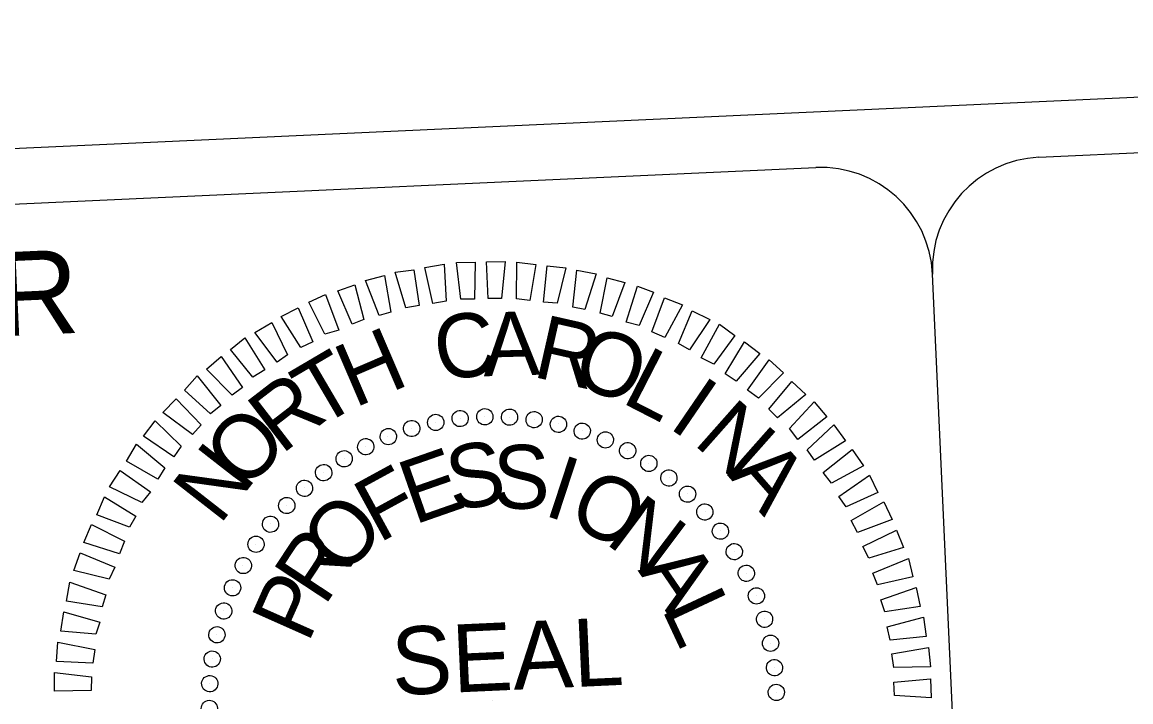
# Model space of a CAD drawing. Extents: x 1190067 to 1192950, y 891516 to 893460.
# Drawn here: x 1191805.2 to 1191884.6, y 892702.5 to 892751.2 of the extents above; entities that cross this region are included whole.
import ezdxf

# ---------------------------------------------------------------- set-up
doc = ezdxf.new("R2010")
doc.units = 0
doc.layers.add('Sheet PE Seal Cell', color=7, linetype='Continuous')
doc.layers.add('Sheet Title CELL', color=7, linetype='Continuous')

msp = doc.modelspace()

# ---------------------------------------------------------------- linework, layer by layer
at = {"layer": 'Sheet PE Seal Cell'}
for p, q in [((1191836.559, 892722.832), (1191836.559, 892722.832)), ((1191838.338, 892722.954), (1191838.338, 892722.954)), ((1191840.123, 892722.914), (1191840.123, 892722.914)), ((1191841.876, 892722.711), (1191841.876, 892722.711)), ((1191833.065, 892722.105), (1191833.065, 892722.105)), ((1191834.831, 892722.51), (1191834.831, 892722.51)), ((1191843.592, 892722.424), (1191843.592, 892722.424)), ((1191845.317, 892721.935), (1191845.317, 892721.935)), ((1191831.388, 892721.542), (1191831.388, 892721.542)), ((1191846.969, 892721.281), (1191846.969, 892721.281)), ((1191829.8, 892720.82), (1191829.8, 892720.82)), ((1191848.583, 892720.544), (1191848.583, 892720.544)), ((1191828.259, 892719.939), (1191828.259, 892719.939)), ((1191850.086, 892719.6), (1191850.086, 892719.6)), ((1191826.764, 892718.938), (1191826.764, 892718.938)), ((1191825.394, 892717.862), (1191825.394, 892717.862)), ((1191851.552, 892718.572), (1191851.552, 892718.572)), ((1191852.862, 892717.416), (1191852.862, 892717.416)), ((1191824.115, 892716.587), (1191824.115, 892716.587)), ((1191854.137, 892716.136), (1191854.137, 892716.136)), ((1191822.958, 892715.277), (1191822.958, 892715.277)), ((1191855.213, 892714.766), (1191855.213, 892714.766)), ((1191821.931, 892713.811), (1191821.931, 892713.811)), ((1191856.214, 892713.271), (1191856.214, 892713.271)), ((1191820.986, 892712.308), (1191820.986, 892712.308)), ((1191857.095, 892711.731), (1191857.095, 892711.731)), ((1191820.249, 892710.694), (1191820.249, 892710.694)), ((1191857.817, 892710.142), (1191857.817, 892710.142)), ((1191819.595, 892709.042), (1191819.595, 892709.042)), ((1191858.38, 892708.465), (1191858.38, 892708.465)), ((1191819.106, 892707.317), (1191819.106, 892707.317)), ((1191858.785, 892706.7), (1191858.785, 892706.7)), ((1191818.82, 892705.601), (1191818.82, 892705.601)), ((1191859.107, 892704.971), (1191859.107, 892704.971)), ((1191818.616, 892703.848), (1191818.616, 892703.848)), ((1191859.229, 892703.193), (1191859.229, 892703.193)), ((1191838.903, 892702.628), (1191838.903, 892702.628))]:
    msp.add_line(p, q, dxfattribs=at)
for points in [[(1191834.602, 892731.054), (1191834.039, 892733.623), (1191835.407, 892733.848), (1191835.567, 892731.22)], [(1191836.616, 892731.349), (1191836.293, 892733.969), (1191837.63, 892733.99), (1191837.588, 892731.353)], [(1191838.559, 892731.397), (1191838.439, 892734.027), (1191839.776, 892734.047), (1191839.532, 892731.401)], [(1191840.588, 892731.368), (1191840.629, 892734.005), (1191841.976, 892733.824), (1191841.566, 892731.251)], [(1191830.75, 892730.188), (1191829.783, 892732.698), (1191831.146, 892733.044), (1191831.59, 892730.43)], [(1191832.671, 892730.722), (1191831.905, 892733.282), (1191833.235, 892733.464), (1191833.637, 892730.888)], [(1191842.545, 892731.133), (1191842.79, 892733.739), (1191844.135, 892733.598), (1191843.521, 892731.056)], [(1191844.628, 892730.783), (1191844.913, 892733.431), (1191846.303, 892733.17), (1191845.487, 892730.619)], [(1191828.832, 892729.574), (1191827.79, 892731.958), (1191829.028, 892732.38), (1191829.668, 892729.896)], [(1191846.594, 892730.346), (1191847.087, 892732.882), (1191848.359, 892732.535), (1191847.457, 892730.101)], [(1191848.448, 892729.701), (1191849.262, 892732.292), (1191850.417, 892731.858), (1191849.392, 892729.46)], [(1191826.879, 892728.836), (1191825.72, 892731.134), (1191826.911, 892731.675), (1191827.879, 892729.125)], [(1191850.304, 892729.015), (1191851.206, 892731.449), (1191852.486, 892730.94), (1191851.215, 892728.611)], [(1191825.138, 892727.904), (1191823.739, 892730.111), (1191824.968, 892730.735), (1191826.011, 892728.309)], [(1191852.208, 892728.17), (1191853.195, 892730.526), (1191854.44, 892729.894), (1191852.999, 892727.72)], [(1191823.442, 892726.854), (1191821.845, 892728.97), (1191823.07, 892729.675), (1191824.189, 892727.375)], [(1191853.836, 892727.15), (1191855.144, 892729.561), (1191856.235, 892728.76), (1191854.748, 892726.705)], [(1191821.708, 892725.761), (1191820.117, 892727.756), (1191821.134, 892728.573), (1191822.576, 892726.287)], [(1191855.55, 892726.012), (1191856.945, 892728.306), (1191858.038, 892727.464), (1191856.344, 892725.481)], [(1191820.227, 892724.477), (1191818.398, 892726.339), (1191819.452, 892727.239), (1191820.971, 892725.038)], [(1191857.145, 892724.828), (1191858.707, 892727.008), (1191859.723, 892726.081), (1191857.941, 892724.256)], [(1191818.666, 892723.149), (1191816.804, 892724.847), (1191817.731, 892725.863), (1191819.408, 892723.75)], [(1191858.666, 892723.479), (1191860.319, 892725.46), (1191861.334, 892724.533), (1191859.302, 892722.859)], [(1191817.395, 892721.672), (1191815.256, 892723.236), (1191816.225, 892724.213), (1191818.013, 892722.349)], [(1191860.149, 892722.087), (1191861.926, 892723.993), (1191862.826, 892722.939), (1191860.752, 892721.304)], [(1191816.05, 892720.069), (1191813.874, 892721.551), (1191814.716, 892722.644), (1191816.583, 892720.824)], [(1191861.434, 892720.565), (1191863.339, 892722.355), (1191864.162, 892721.216), (1191861.955, 892719.818)], [(1191814.906, 892718.477), (1191812.659, 892719.752), (1191813.374, 892720.961), (1191815.397, 892719.269)], [(1191862.562, 892718.954), (1191864.636, 892720.59), (1191865.46, 892719.411), (1191863.166, 892718.171)], [(1191813.767, 892716.803), (1191811.445, 892717.913), (1191812.203, 892719.083), (1191814.381, 892717.561)], [(1191863.696, 892717.222), (1191865.896, 892718.742), (1191866.48, 892717.512), (1191864.216, 892716.476)], [(1191812.875, 892715.019), (1191810.523, 892715.925), (1191811.072, 892717.206), (1191813.326, 892715.81)], [(1191864.584, 892715.519), (1191866.916, 892716.842), (1191867.501, 892715.572), (1191865.03, 892714.648)], [(1191812.151, 892713.121), (1191809.6, 892713.936), (1191810.15, 892715.218), (1191812.515, 892714.029)], [(1191865.4, 892713.651), (1191867.819, 892714.816), (1191868.322, 892713.582), (1191865.843, 892712.82)], [(1191811.423, 892711.303), (1191808.882, 892711.917), (1191809.35, 892713.195), (1191811.83, 892712.173)], [(1191866.136, 892711.739), (1191868.682, 892712.788), (1191868.986, 892711.464), (1191866.458, 892710.902)], [(1191810.905, 892709.334), (1191808.373, 892709.745), (1191808.595, 892711.093), (1191811.19, 892710.198)], [(1191866.71, 892709.819), (1191869.224, 892710.704), (1191869.529, 892709.34), (1191866.992, 892708.981)], [(1191810.468, 892707.368), (1191807.945, 892707.577), (1191808.165, 892708.965), (1191810.753, 892708.232)], [(1191867.163, 892707.894), (1191869.767, 892708.58), (1191869.951, 892707.21), (1191867.369, 892706.93)], [(1191810.239, 892705.289), (1191807.639, 892705.414), (1191807.738, 892706.797), (1191810.397, 892706.27)], [(1191867.495, 892705.963), (1191870.11, 892706.407), (1191870.253, 892705.035), (1191867.62, 892704.996)], [(1191810.126, 892703.338), (1191807.492, 892703.299), (1191807.512, 892704.638), (1191810.162, 892704.313)], [(1191867.628, 892703.942), (1191870.252, 892704.184), (1191870.315, 892702.808), (1191867.672, 892702.971)]]:
    msp.add_lwpolyline(points, close=True, dxfattribs=at)
for centre, major_axis in [((1191836.561, 892722.807), (-0.067, 0.579)), ((1191838.329, 892722.934), (-0.016, 0.583)), ((1191840.101, 892722.907), (0.034, 0.582)), ((1191833.092, 892722.094), (-0.167, 0.559)), ((1191834.811, 892722.526), (-0.117, 0.571)), ((1191841.863, 892722.726), (0.085, 0.577)), ((1191843.604, 892722.391), (0.135, 0.567)), ((1191831.418, 892721.513), (-0.215, 0.542)), ((1191845.308, 892721.906), (0.184, 0.553)), ((1191846.964, 892721.274), (0.231, 0.535)), ((1191829.8, 892720.789), (-0.261, 0.521)), ((1191848.559, 892720.501), (0.277, 0.513)), ((1191828.252, 892719.927), (-0.306, 0.497)), ((1191850.08, 892719.591), (0.321, 0.487)), ((1191826.785, 892718.933), (-0.348, 0.468)), ((1191851.516, 892718.553), (0.362, 0.457)), ((1191825.41, 892717.814), (-0.387, 0.436)), ((1191852.856, 892717.393), (0.401, 0.424)), ((1191824.138, 892716.581), (-0.424, 0.401)), ((1191854.089, 892716.12), (0.436, 0.387)), ((1191822.978, 892715.241), (-0.457, 0.362)), ((1191855.208, 892714.745), (0.468, 0.348)), ((1191821.939, 892713.805), (-0.487, 0.321)), ((1191856.202, 892713.278), (0.497, 0.306)), ((1191821.03, 892712.284), (-0.513, 0.277)), ((1191857.064, 892711.73), (0.521, 0.261)), ((1191820.256, 892710.689), (-0.535, 0.231)), ((1191857.788, 892710.112), (0.542, 0.215)), ((1191819.624, 892709.033), (-0.553, 0.184)), ((1191858.369, 892708.438), (0.559, 0.167)), ((1191819.139, 892707.329), (-0.567, 0.135)), ((1191858.801, 892706.719), (0.571, 0.117)), ((1191818.805, 892705.588), (-0.577, 0.085)), ((1191859.082, 892704.969), (0.579, 0.067)), ((1191818.623, 892703.826), (-0.582, 0.034)), ((1191859.209, 892703.202), (0.583, 0.016)), ((1191818.596, 892702.054), (-0.583, -0.016))]:
    msp.add_ellipse(centre, major_axis=major_axis, ratio=0.999708, dxfattribs=at)
at = {"layer": 'Sheet Title CELL'}
for p, q in [((1190867.084, 892699.262), (1192001.897, 892751.18)), ((1191878.026, 892741.509), (1192002.08, 892747.184)), ((1191702.394, 892733.474), (1191862.043, 892740.778)), ((1191876.25, 892605.285), (1191870.4, 892733.151))]:
    msp.add_line(p, q, dxfattribs=at)
for centre, start, end in [((1191878.392, 892733.517), 92.61947, 182.61947), ((1191862.409, 892732.786), 2.61947, 92.61947)]:
    msp.add_arc(centre, 8, start, end, dxfattribs=at)

# ---------------------------------------------------------------- texts
at = {"layer": 'Sheet PE Seal Cell'}
for s, height, rotation, p in [('C', 4.567, 8.83934, (1191835.062, 892725.439)), ('A', 4.566, 1.63979, (1191838.247, 892725.828)), ('R', 4.567, 347.24056, (1191841.653, 892725.822)), ('H', 4.567, 23.23894, (1191828.986, 892723.54)), ('O', 4.567, 340.04063, (1191844.391, 892725.339)), ('T', 4.567, 30.43924, (1191826.417, 892722.084)), ('L', 4.567, 332.84034, (1191848.02, 892724.005)), ('R', 4.567, 37.63997, (1191823.748, 892720.178)), ('I', 4.566, 325.63961, (1191851.386, 892722.213)), ('N', 4.567, 318.43837, (1191853.183, 892721.039)), ('O', 4.567, 44.84121, (1191821.071, 892717.542)), ('S', 4.567, 9.87507, (1191836.013, 892716.158)), ('N', 4.567, 52.04297, (1191819.317, 892715.111)), ('E', 4.567, 19.23053, (1191833.261, 892715.181)), ('S', 4.567, 0.51987, (1191838.924, 892716.332)), ('A', 4.567, 311.23662, (1191855.679, 892718.761)), ('F', 4.566, 28.5865, (1191830.727, 892713.849)), ('I', 4.567, 341.80907, (1191842.43, 892715.925)), ('O', 4.567, 332.45295, (1191844.074, 892715.432)), ('N', 4.567, 323.09608, (1191846.859, 892713.938)), ('O', 4.567, 47.30071, (1191828.166, 892711.34)), ('R', 4.568, 56.65912, (1191826.84, 892709.292)), ('A', 4.568, 304.37973, (1191849.261, 892711.94)), ('P', 4.568, 66.01836, (1191825.664, 892706.644)), ('L', 4.568, 295.02032, (1191850.966, 892709.22)), ('SEAL', 4.8585, 2.61947, (1191831.752, 892702.989))]:
    msp.add_text(s, height=height, rotation=rotation, dxfattribs=at).set_placement(p)
at = {"layer": 'Sheet Title CELL'}
msp.add_text(' HYDRAULICS ENGINEER', height=6, rotation=2.61947, dxfattribs=at).set_placement((1191711.375, 892724.465))

doc.saveas('drawing.dxf')
